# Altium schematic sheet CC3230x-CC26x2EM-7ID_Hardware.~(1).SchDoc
size 558 x 431 mm; Date: Not shown in title block; ApprovedBy: Not shown in title block; CheckedBy: Not shown in title block; Author: Not shown in title block; CompanyName: Not shown in title block; Engineer: Not shown in title block; Organization: Not shown in title block; Address1: Not shown in title block; Address2: Not shown in title block; Address3: Not shown in title block; Address4: Not shown in title block; DocumentNumber: 5; Revision: Use project parameter SCH_Rev; SheetNumber: 5; SheetTotal: 5; PageSetup: Record=PageOptions¦CenterHorizontal=True¦CenterVertical=True¦PrintScale=1.00¦XCorrection=1.00¦YCorrection=1.00¦PrintKind=0¦BorderSize=5000000¦LeftOffset=0¦BottomOffset=0¦Orientation=2¦PaperLength=1000¦PaperWidth=1000¦Scale=100¦PaperSource=15¦PrintQuality=600¦MediaType=1¦DitherType=10¦PaperKind=Letter¦PrintScaleMode=1
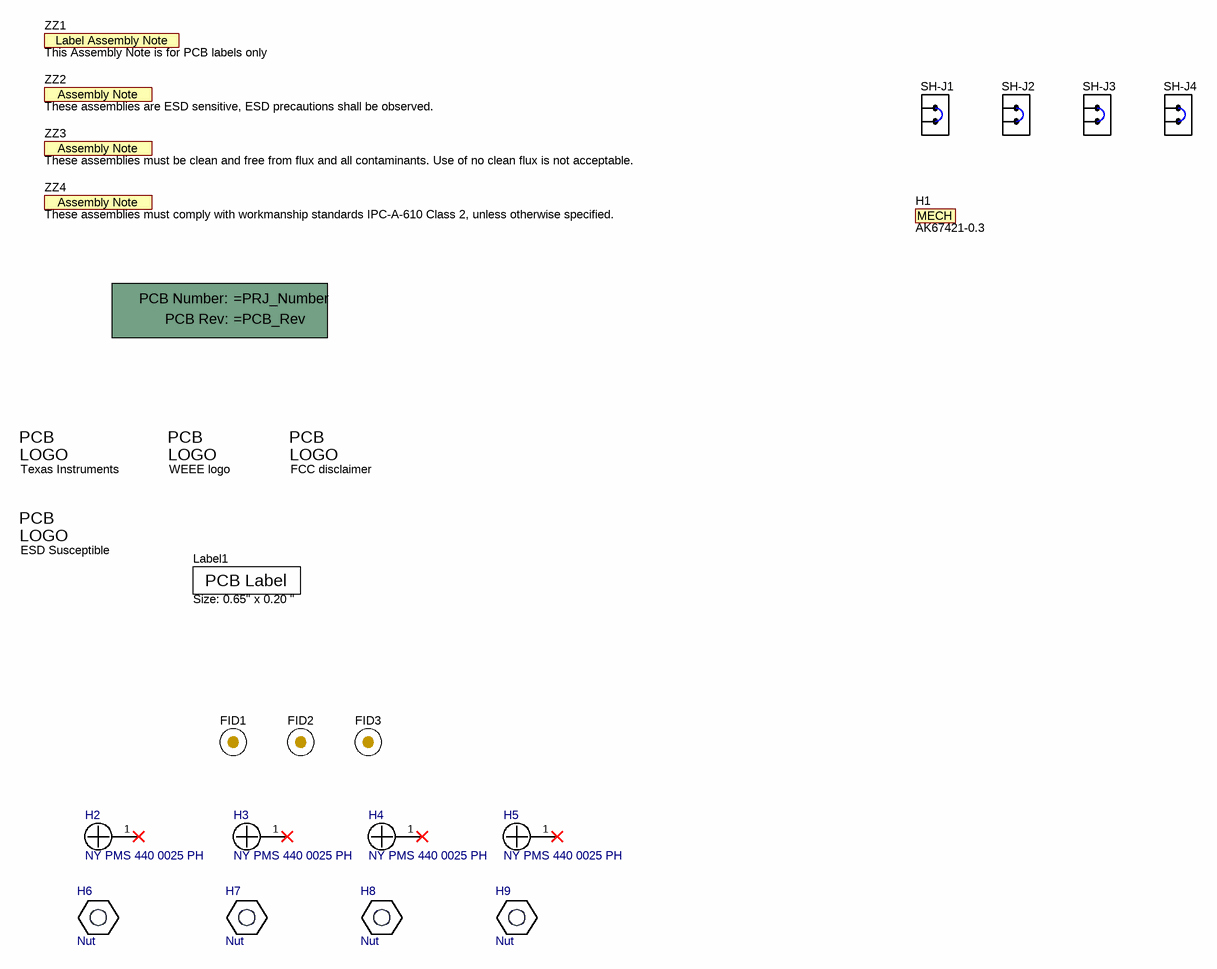
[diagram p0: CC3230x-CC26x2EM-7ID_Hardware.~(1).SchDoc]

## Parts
FID1  CMP-0077181-1  [Fiducial10-20]  (value not drawn)  (no BOM)
FID2  CMP-0077181-1  [Fiducial10-20]  (value not drawn)  (no BOM)
FID3  CMP-0077181-1  [Fiducial10-20]  (value not drawn)  (no BOM)
H1  AK67421-0.3  (mechanical)
H2  NY PMS 440 0025 PH  [NY PMS 440 0025 PH]
H3  NY PMS 440 0025 PH  [NY PMS 440 0025 PH]
H4  NY PMS 440 0025 PH  [NY PMS 440 0025 PH]
H5  NY PMS 440 0025 PH  [NY PMS 440 0025 PH]
H6  Nut  [Keystone_1902C]
H7  Nut  [Keystone_1902C]
H8  Nut  [Keystone_1902C]
H9  Nut  [Keystone_1902C]
Label1  Note: Size: 0.65" x 0.20 "  [Label_650x200]  (hidden comment: CMP-0003625-1)
Logo1  Texas Instruments  [TI_Stacked_Overlay_Small]  (no BOM)
Logo2  WEEE logo  [WEEE_Minimum]  (no BOM)
Logo3  FCC disclaimer  [FCC_disclaimer_stacked]  (no BOM)
Logo4  ESD Susceptible  [ESD_Overlay_Medium]  (no BOM)
PCB1  Printed Circuit Board  (value not drawn)  (mechanical)
SH-J1  60900213421  [Wurth_60900213421]  (value not drawn)
SH-J2  60900213421  [Wurth_60900213421]  (value not drawn)
SH-J3  60900213421  [Wurth_60900213421]  (value not drawn)
SH-J4  60900213421  [Wurth_60900213421]  (value not drawn)
ZZ1  This Assembly Note is for PCB labels only  [AssemblyNoteLabel]  (no BOM)
ZZ2  These assemblies are ESD sensitive, ESD precautions shall be observed.  [AssemblyNote]  (no BOM)
ZZ3  These assemblies must be clean and free from flux and all contaminants. Use of no clean flux is not acceptable.  [AssemblyNote]  (no BOM)
ZZ4  These assemblies must comply with workmanship standards IPC-A-610 Class 2, unless otherwise specified.  [AssemblyNote]  (no BOM)

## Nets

Not connected (* = marked no-connect by the designer): H2 1*; H3 1*; H4 1*; H5 1*

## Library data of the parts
FID1-FID3 = CMP-0077181-1: Fiducial mark.  There is nothing to buy or mount.
H1 = CMP-0077983-1: Cable, USB-A to micro USB-B, 0.3 m; Manufacturer: Assman WSW
H2-H5 = CMP-0003617-1: Machine Screw, Round, #4-40 x 1/4, Nylon, Philips panhead; Manufacturer: B&F Fastener Supply; CompType: Hardware
H6-H9 = CMP-0003610-1: Standoff, Hex, 0.5"L #4-40 Nylon; Manufacturer: Keystone; PartNumber: 1902C; CompType: Hardware
Label1 = CMP-0003625-1: Thermal Transfer Printable Labels, 0.650" W x 0.200" H - 10,000 per roll; Manufacturer: Brady; PartNumber: THT-14-423-10; Alternate Manufacturer: ----; CompType: Label
Logo1 = CMP-0074838-1: Texas Instrument Corporate Signature; SymbolCreator: a0412235; Library Reference: Logo; Lib Reference: TI_Logo
Logo2 = CMP-0074769-1
Logo3 = CMP-0074847-1: FCC_disclaimer; Library Reference: Logo
Logo4 = CMP-0074840-1: ESD Susceptible Symbol; SymbolCreator: a0412235; Library Reference: Logo; Lib Reference: ESD_Susceptible
PCB1 = CMP-0003618-2: Manufacturer: Any; Alternate Manufacturer: ----; CompType: PCB
SH-J1-SH-J4 = CMP-0003761-2: Shunt, 2.54mm, Gold, Black; Manufacturer: Wurth Elektronik
ZZ1 = CMP-0003616-3
ZZ2 = CMP-0077236-1
ZZ3 = CMP-0077237-1
ZZ4 = CMP-0077238-1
